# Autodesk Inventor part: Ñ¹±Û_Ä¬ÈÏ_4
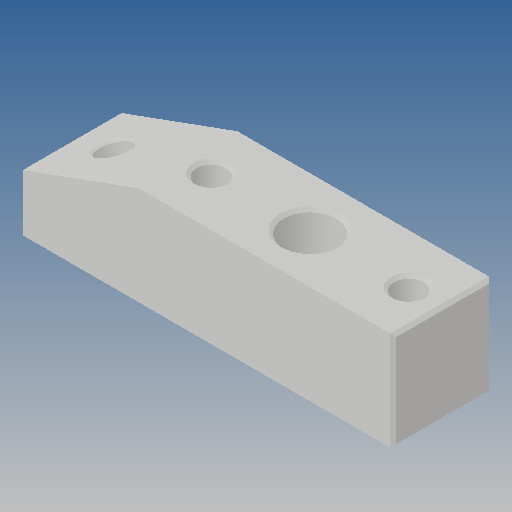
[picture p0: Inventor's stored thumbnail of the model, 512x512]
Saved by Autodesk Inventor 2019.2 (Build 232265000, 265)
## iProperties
Created: 2013-03
Part Number: Ñ¹±Û_Ä¬ÈÏ_4
Material: Ogólny
Document SubType Name: Modeling
Designer: CADENGINEERING4
Density: 1 g/cm^3
Appearance: Domyślna
Author: CADENGINEERING4
Revision Number: ÈÎºÎ
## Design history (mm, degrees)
feature "NONE"
node "Bryła1"
